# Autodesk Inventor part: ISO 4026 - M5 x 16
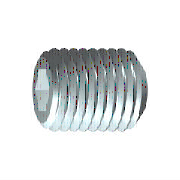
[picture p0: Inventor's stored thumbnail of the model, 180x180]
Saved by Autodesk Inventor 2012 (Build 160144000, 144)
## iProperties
Created: 2010-01
Part Number: ISO 4026 - M5 x 16
Material: Stainless Steel, 440C
Description: Hexagon socket set screws with flat point
Document SubType Name: Modeling
Standard: ISO 4026
Designer: sauflet
Standard Revision: Third edition 2003-12-01
Standards Organization: ISO
Language: en-US
Size Designation: M5 x 16
Categories: <MemberInstance><Categories><Category DisplayName="Fasteners" InternalName="e4da775c-781d-43d5-af7c-5136215cf5a6" Mnemonic="FSTN"><Category DisplayName="Bolts"
Density: 7.75 g/cm^3
IsCustomPart: 0
Author: sauflet
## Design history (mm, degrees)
revolve "Body" stored, may be unused: angle "d6" = 90 deg
sketch "Sketch2"
  geometry: L1 (-0.722, 1.25)-(0.722, 1.25); L2 (0.722, 1.25)-(1.443, 0); L3 (1.443, 0)-(0.722, -1.25); L4 (0.722, -1.25)-(-0.722, -1.25); L5 (-0.722, -1.25)-(-1.443, 0); L6 (-1.443, 0)-(-0.722, 1.25); A1 r 1.443 centre (0, 0) between (-0.722, 1.25) and (0.722, 1.25) reference; 2 further points
  constraints: 12 end point, 2 point on circle, 1 coincident, 1 horizontal, 11 other
extrude "Slot" join sketch "Sketch2" taper "d9" = 0 deg; stored distance "d21" = 10
workaxis "Work Axis1"
workplane "Work Plane1"
body "Solid1"
chamfer "Chamfer1" distance "d7" = 0.49076 (= -0.5 x GD1 + 0.5 x NND); stored, may be unused: angle "d8" = 45 deg (= FAWI), second distance "d29" = 0.49076 (= -0.5 x GD1 + 0.5 x NND)
feature "Thread" dims "d11" = 16 (= NLG), "d12" = 0
chamfer "Chamfer2" distance "d13" = 0.49076 (= -0.5 x GD1 + 0.5 x NND); stored, may be unused: angle "d14" = 45 deg (= FAWI), second distance "d30" = 0.49076 (= -0.5 x GD1 + 0.5 x NND)
sketch "Sketch1"
  geometry: L1 (0, 0)-(12.167, 0); L2 (16, 1.443)-(16, 2.5); L3 (16, 2.5)-(0, 2.5); L4 (16, 1.443)-(13, 1.443); L5 (13, 1.443)-(12.167, 0); L6 (0, -0.5)-(0, 3) reference; L7 (0, 2.5)-(0, 0)
  constraints: 13 end point, 3 parallel, 1 collinear, 1 perpendicular, 1 point on line
  dimensions: "d0" = 3 distance of L2.start L4.end (= INTI); "d1" = 60 deg angle of L5 L1; "d2" = 5 diameter of L3 L1 (= NND); "d3" = 2.88675 diameter of L4 L1 (= 1.1547 x SW); "d5" = 16 distance from line of L2 L3.end (= NLG)
other parameters: "NND" = 5 [user parameter; used in 5 equation terms], "NLG" = 16 [user parameter; used in 2 equation terms], "INTI" = 3 [user parameter; used in 1 equation term], "FAWI" = 45 deg [user parameter; used in 2 equation terms], "SW" = 2.5 [user parameter; used in 2 equation terms], "GD1" = 4.01848 (= THREADDIA - 1.2269 x PTC) [user parameter; used in 4 equation terms], "d4" = 0, "FAWI1" = 45 deg [user parameter], "d15" = 0, "d31" = 0, "GUL" = 0.49076 (= 0.61345 x PTC) [user parameter], "SPD" = 3.5 [user parameter], "SEWI" = 90 deg [user parameter], "TOA" = 30 deg [user parameter], "THREADDIA" = 5 [user parameter; used in 1 equation term], "TPU" = 12.5 (computed from PTC) [user parameter], "PTC" = 0.8 [user parameter; used in 4 equation terms], "GAL" = 0.49076 (= 0.61345 x PTC) [user parameter], "E0" = 2.8875 (= 1.155 x SW) [user parameter]
